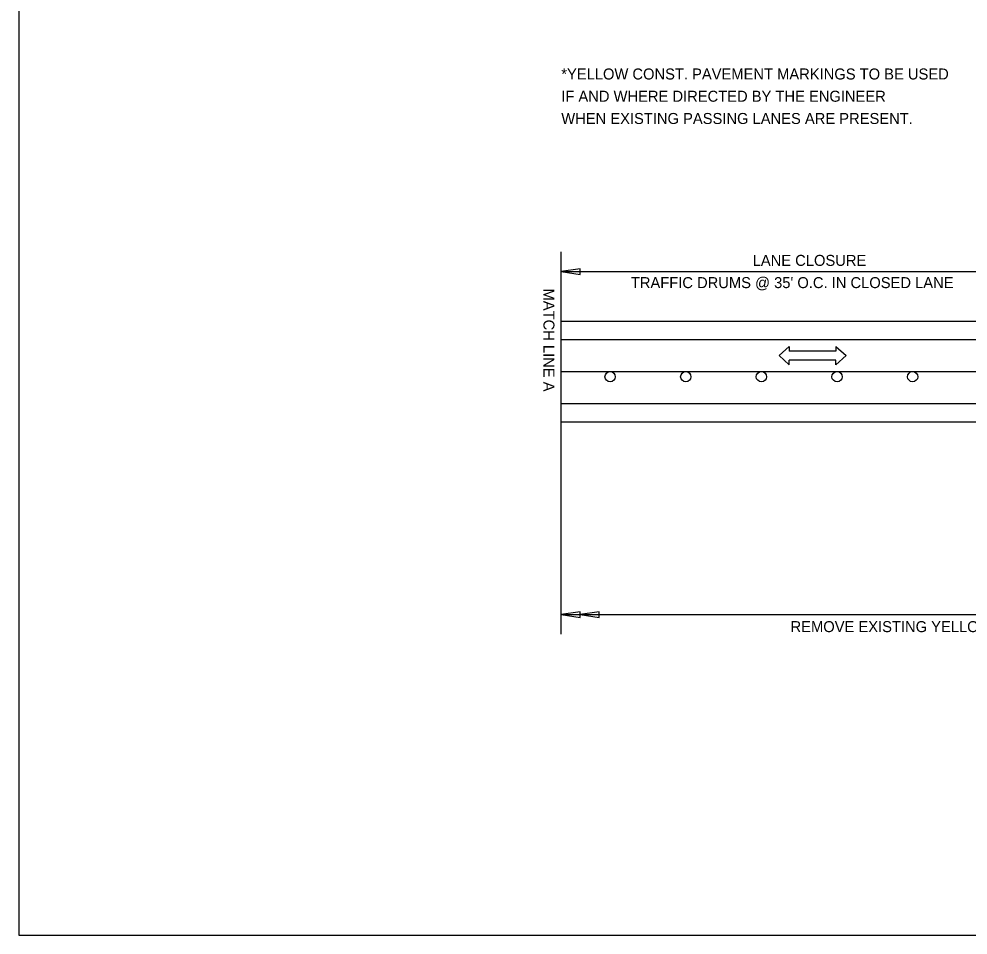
# Model space of a CAD drawing. Extents: x 1806907 to 1812607, y 675071 to 676228.
# Drawn here: x 1808932 to 1809449, y 675071 to 675571 of the extents above; entities that cross this region are included whole.
import ezdxf

# ---------------------------------------------------------------- set-up
doc = ezdxf.new("R2010")
doc.units = 0
for name, color, linetype in [('Default', 7, 'Continuous'), ('DSN_DRFT_Named-Boundary', 7, 'Continuous'), ('R_MOT', 7, 'Continuous')]:
    doc.layers.add(name, color=color, linetype=linetype)

msp = doc.modelspace()

# ---------------------------------------------------------------- linework, layer by layer
at = {"layer": 'Default'}
for p, q in [((1809227.42, 675235.2), (1809227.42, 675443.73)), ((1809237.73, 675434.49), (1809227.42, 675432.94)), ((1809237.73, 675431.4), (1809237.73, 675434.49)), ((1809227.42, 675432.94), (1809501.54, 675432.94)), ((1809227.42, 675432.94), (1809237.73, 675431.4)), ((1809227.42, 675405.87), (1809377.42, 675405.87)), ((1809377.42, 675405.86), (1810285.94, 675405.86)), ((1809227.42, 675395.87), (1809377.42, 675395.87)), ((1809377.42, 675395.86), (1809647.71, 675395.86)), ((1809227.42, 675378.48), (1809748.63, 675378.48)), ((1809227.42, 675361.1), (1809377.42, 675361.1)), ((1809377.42, 675361.1), (1809502.12, 675361.1)), ((1809227.42, 675351.1), (1809377.42, 675351.1)), ((1809377.42, 675351.1), (1810285.94, 675351.1)), ((1809237.73, 675247.53), (1809227.42, 675245.99)), ((1809237.73, 675244.44), (1809237.73, 675247.53)), ((1809248.03, 675247.53), (1809237.73, 675245.99)), ((1809248.03, 675244.44), (1809248.03, 675247.53)), ((1809227.42, 675245.99), (1809750.78, 675245.99)), ((1809227.42, 675245.99), (1809237.73, 675244.44)), ((1809237.73, 675245.99), (1809248.03, 675244.44))]:
    msp.add_line(p, q, dxfattribs=at)
msp.add_lwpolyline([(1809227.42, 675378.48), (1809501.54, 675378.48)], dxfattribs=at)
for centre in [(1809254.06, 675375.67), (1809295.3, 675375.67), (1809336.55, 675375.67), (1809377.8, 675375.67), (1809419.04, 675375.67)]:
    msp.add_circle(centre, 2.81, dxfattribs=at)
at = {"layer": 'DSN_DRFT_Named-Boundary'}
msp.add_lwpolyline([(1808931.68, 675071.2), (1810581.68, 675071.2), (1810581.68, 676070.26), (1808931.68, 676070.26)], close=True, dxfattribs=at)
at = {"layer": 'R_MOT'}
for p, q in [((1809346.26, 675387.17), (1809351.74, 675392.17)), ((1809351.74, 675382.17), (1809346.26, 675387.17)), ((1809351.74, 675392.17), (1809351.74, 675389.67)), ((1809377.22, 675389.67), (1809351.74, 675389.67)), ((1809377.22, 675392.17), (1809382.7, 675387.17)), ((1809377.22, 675392.17), (1809377.22, 675389.67)), ((1809382.7, 675387.17), (1809377.22, 675382.17)), ((1809377.22, 675384.67), (1809351.74, 675384.67)), ((1809351.74, 675382.17), (1809351.74, 675384.67)), ((1809377.22, 675382.17), (1809377.22, 675384.67))]:
    msp.add_line(p, q, dxfattribs=at)

# ---------------------------------------------------------------- texts
at = {"layer": 'Default'}
for s, p in [('*YELLOW CONST. PAVEMENT MARKINGS TO BE USED', (1809227.42, 675537.73)), ('IF AND WHERE DIRECTED BY THE ENGINEER', (1809227.42, 675525.6)), ('WHEN EXISTING PASSING LANES ARE PRESENT.', (1809227.42, 675513.47)), ('LANE CLOSURE', (1809331.79, 675436.09)), ("TRAFFIC DRUMS @ 35' O.C. IN CLOSED LANE", (1809265.36, 675423.96)), ('REMOVE EXISTING YELLOW PAVEMENT MARKINGS ALONG C.L.', (1809352.47, 675236.37))]:
    msp.add_text(s, height=6, dxfattribs=at).set_placement(p)
msp.add_text('MATCH LINE A', height=6, rotation=270, dxfattribs=at).set_placement((1809217.67, 675423.74))

doc.saveas('drawing.dxf')
